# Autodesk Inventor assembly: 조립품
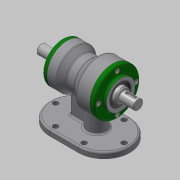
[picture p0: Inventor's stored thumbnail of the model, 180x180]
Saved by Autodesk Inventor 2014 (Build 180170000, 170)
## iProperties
Created: 2020-01
Part Number: 조립품
Document SubType Name: Assembly
Designer: kh
Author: kh
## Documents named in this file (10)
- C:\Users\kh\Desktop\700104V1034\조립품.iam
- C:\Users\kh\Desktop\700104V1034\본체.ipt
- C:\Users\kh\Desktop\700104V1034\축.ipt
- C:\Users\kh\Desktop\700104V1034\베어링 6203.ipt
- C:\Users\kh\Desktop\700104V1034\베어링 6205.ipt
- C:\Users\kh\Desktop\700104V1034\앞커버.ipt
- C:\Users\kh\Desktop\700104V1034\뒤커버.ipt
- C:\Users\kh\Desktop\700104V1034\오일 실 17 30 8.ipt
- C:\Users\kh\Desktop\700104V1034\오일 실 25 38 8.ipt
- C:\Users\kh\Desktop\700104V1034\볼트 M4.ipt
